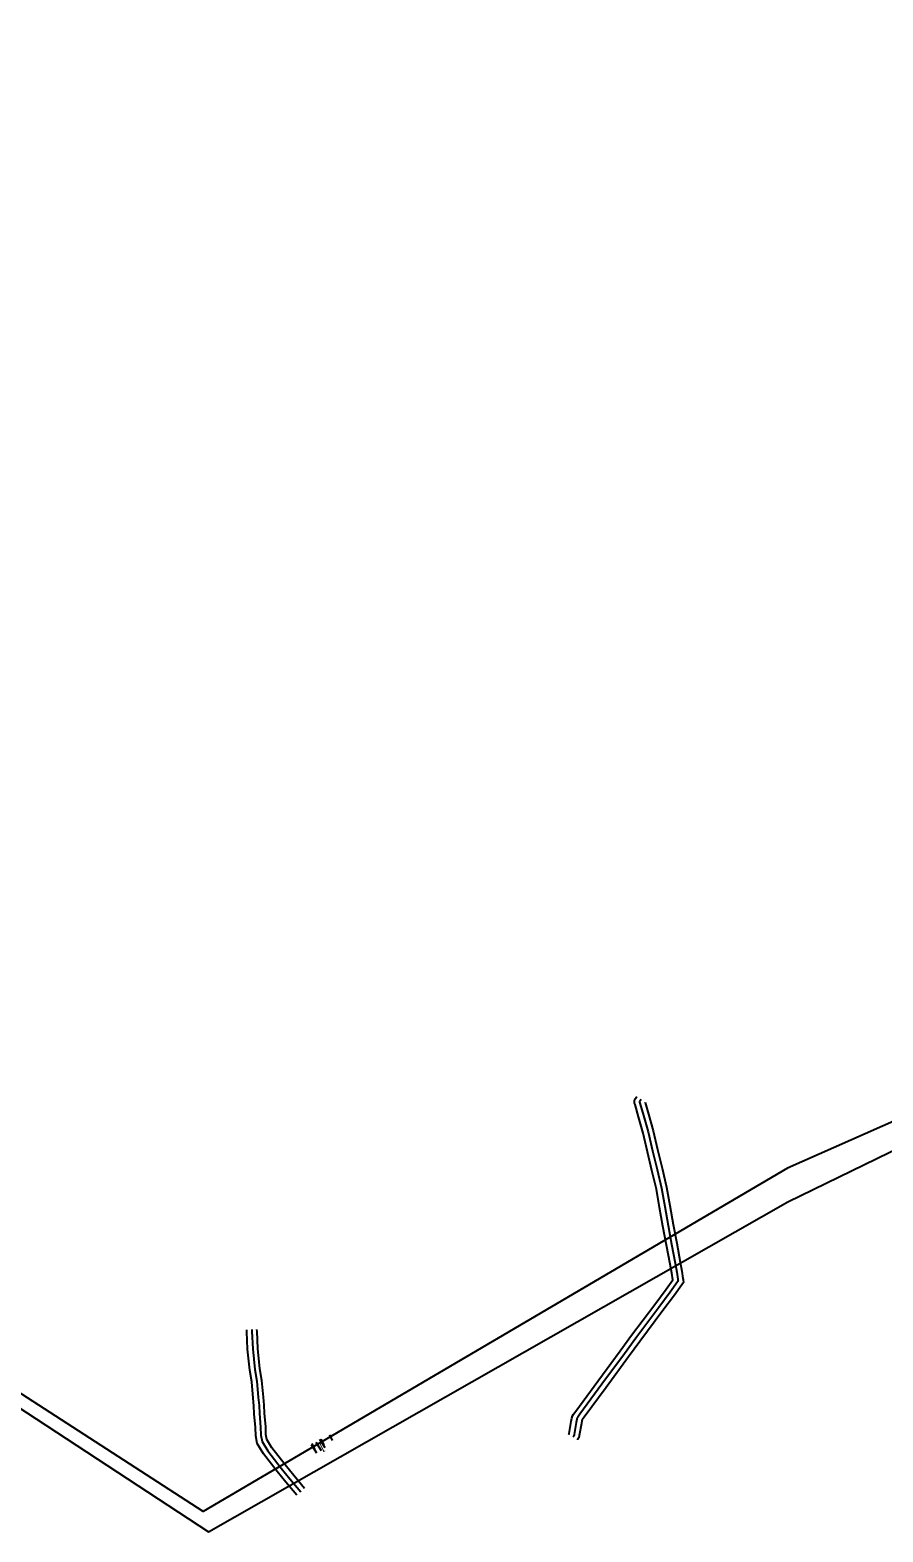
# Model space of a CAD drawing. Extents: x -642867 to -641789, y -1114889 to -1114420.
# Drawn here: x -642321.9 to -642055.5, y -1114889.2 to -1114419.9 of the extents above; entities that cross this region are included whole.
import ezdxf

# ---------------------------------------------------------------- set-up
doc = ezdxf.new("R2010")
doc.units = 0
for name, color, linetype in [('K Stoka', 7, 'Continuous'), ('K Stoka - ochranné pásmo tisk', 7, 'Continuous'), ('K Výúsť', 7, 'Continuous'), ('VP Řad', 7, 'Continuous'), ('VP Řad - ochranné pásmo tisk', 7, 'Continuous'), ('Žádost o vyjádření k existenci sítí', 7, 'Continuous')]:
    doc.layers.add(name, color=color, linetype=linetype)

msp = doc.modelspace()

# ---------------------------------------------------------------- linework, layer by layer
at = {"layer": 'K Stoka'}
msp.add_line((-642232.66, -1114861.12), (-642230.97, -1114863.74), dxfattribs=at)
msp.add_lwpolyline([(-642231.03, -1114860.19), (-642230.17, -1114861.96)], dxfattribs=at)
at = {"layer": 'K Stoka - ochranné pásmo tisk'}
for points in [[(-642227.38, -1114860.61), (-642228.24, -1114858.84)], [(-642232.28, -1114864.58), (-642233.96, -1114861.96)], [(-642232.96, -1114863.31), (-642233.82, -1114861.54)], [(-642229.67, -1114862.9), (-642231.36, -1114860.28)]]:
    msp.add_lwpolyline(points, dxfattribs=at)
at = {"layer": 'VP Řad'}
for points in [[(-642131.07, -1114754.01), (-642131.45, -1114754.55), (-642131.53, -1114754.7), (-642131.52, -1114754.86), (-642131.42, -1114755.16), (-642130.27, -1114759.04), (-642128.88, -1114764.18), (-642127.48, -1114770.05), (-642126.09, -1114775.88), (-642124.7, -1114781.72), (-642123.68, -1114787.46), (-642122.63, -1114793.37), (-642121.52, -1114799.28), (-642120.42, -1114805.18), (-642119.92, -1114808), (-642119.58, -1114810.16), (-642119.55, -1114810.41), (-642119.54, -1114810.55), (-642119.51, -1114810.8), (-642119.65, -1114811), (-642121.94, -1114814.22), (-642125.53, -1114819.03), (-642132.71, -1114828.66), (-642136.28, -1114833.5), (-642143.3, -1114843.02), (-642150.17, -1114852.32), (-642150.83, -1114853.26), (-642151, -1114853.53), (-642151.11, -1114853.94), (-642151.29, -1114854.95), (-642151.95, -1114858.72), (-642152.01, -1114859.06), (-642152.22, -1114859.33), (-642152.34, -1114859.53)], [(-642252.62, -1114825.93), (-642252.6, -1114826.56), (-642252.36, -1114831.91), (-642251.66, -1114838.42), (-642251.08, -1114842.04), (-642250.61, -1114847.2), (-642250.36, -1114849.64), (-642250.25, -1114852.13), (-642249.88, -1114856.43), (-642249.82, -1114858.93), (-642249.43, -1114860.91), (-642247.65, -1114863.79), (-642243.48, -1114869.23), (-642240.77, -1114872.58), (-642237.36, -1114876.58)]]:
    msp.add_lwpolyline(points, dxfattribs=at)
at = {"layer": 'VP Řad - ochranné pásmo tisk'}
for points in [[(-642153.72, -1114858.7), (-642153.55, -1114858.42), (-642153.53, -1114858.39), (-642152.88, -1114854.67), (-642152.69, -1114853.59), (-642152.49, -1114852.88), (-642152.17, -1114852.37), (-642151.48, -1114851.38), (-642144.6, -1114842.06), (-642137.58, -1114832.54), (-642134.01, -1114827.7), (-642126.82, -1114818.07), (-642123.24, -1114813.27), (-642121.18, -1114810.37), (-642121.51, -1114808.27), (-642122.01, -1114805.47), (-642123.1, -1114799.58), (-642124.22, -1114793.66), (-642125.27, -1114787.74), (-642126.28, -1114782.05), (-642127.66, -1114776.25), (-642129.05, -1114770.42), (-642130.44, -1114764.58), (-642131.82, -1114759.48), (-642132.96, -1114755.64), (-642133.12, -1114755.17), (-642133.17, -1114754.34), (-642132.83, -1114753.7), (-642132.39, -1114753.08)], [(-642129.75, -1114754.94), (-642129.79, -1114754.99), (-642128.72, -1114758.6), (-642127.32, -1114763.78), (-642125.91, -1114769.67), (-642124.52, -1114775.51), (-642123.12, -1114781.39), (-642122.09, -1114787.18), (-642121.04, -1114793.08), (-642119.94, -1114798.98), (-642118.83, -1114804.89), (-642118.33, -1114807.73), (-642117.98, -1114809.95), (-642117.95, -1114810.23), (-642117.93, -1114810.38), (-642117.84, -1114811.23), (-642118.33, -1114811.93), (-642120.64, -1114815.17), (-642124.24, -1114819.99), (-642131.41, -1114829.62), (-642134.98, -1114834.46), (-642142, -1114843.98), (-642148.86, -1114853.26), (-642149.49, -1114854.15), (-642149.51, -1114854.18), (-642149.53, -1114854.29), (-642149.7, -1114855.23), (-642150.36, -1114859), (-642150.49, -1114859.73), (-642150.89, -1114860.24), (-642150.96, -1114860.36)], [(-642238.58, -1114877.62), (-642242.01, -1114873.6), (-642244.74, -1114870.22), (-642248.97, -1114864.7), (-642250.95, -1114861.5), (-642251.41, -1114859.1), (-642251.48, -1114856.52), (-642251.85, -1114852.23), (-642251.96, -1114849.76), (-642252.2, -1114847.35), (-642252.67, -1114842.24), (-642253.25, -1114838.63), (-642253.96, -1114832.03), (-642254.19, -1114826.62), (-642254.22, -1114825.99)], [(-642236.14, -1114875.54), (-642239.54, -1114871.55), (-642242.22, -1114868.24), (-642246.33, -1114862.88), (-642247.92, -1114860.32), (-642248.22, -1114858.75), (-642248.29, -1114856.34), (-642248.65, -1114852.03), (-642248.76, -1114849.52), (-642249.02, -1114847.04), (-642249.49, -1114841.84), (-642250.08, -1114838.2), (-642250.77, -1114831.79), (-642251, -1114826.5), (-642251.02, -1114825.88)]]:
    msp.add_lwpolyline(points, dxfattribs=at)
at = {"layer": 'Žádost o vyjádření k existenci sítí'}
msp.add_lwpolyline([(-641864.28, -1114677.72), (-642085.39, -1114775.48), (-642267.87, -1114882.75), (-642367.02, -1114818.64), (-642423.86, -1114779.32), (-642601.21, -1114710.09), (-642652.07, -1114689.57), (-642690.96, -1114580.59), (-642714.46, -1114510.07), (-642768.31, -1114479.3), (-642862.33, -1114419.89), (-642866.6, -1114425.45), (-642716.17, -1114513.92), (-642655.06, -1114692.56), (-642427.71, -1114783.17), (-642266.16, -1114889.16), (-642085.25, -1114786.03), (-641870.76, -1114681.52), (-641855.27, -1114676.17), (-641857.52, -1114671.94)], close=True, dxfattribs=at)

# ---------------------------------------------------------------- texts
at = {"layer": 'K Výúsť'}
msp.add_text('[', height=2.5, rotation=25.914, dxfattribs=at).set_placement((-642230.75, -1114863.63))

doc.saveas('drawing.dxf')
